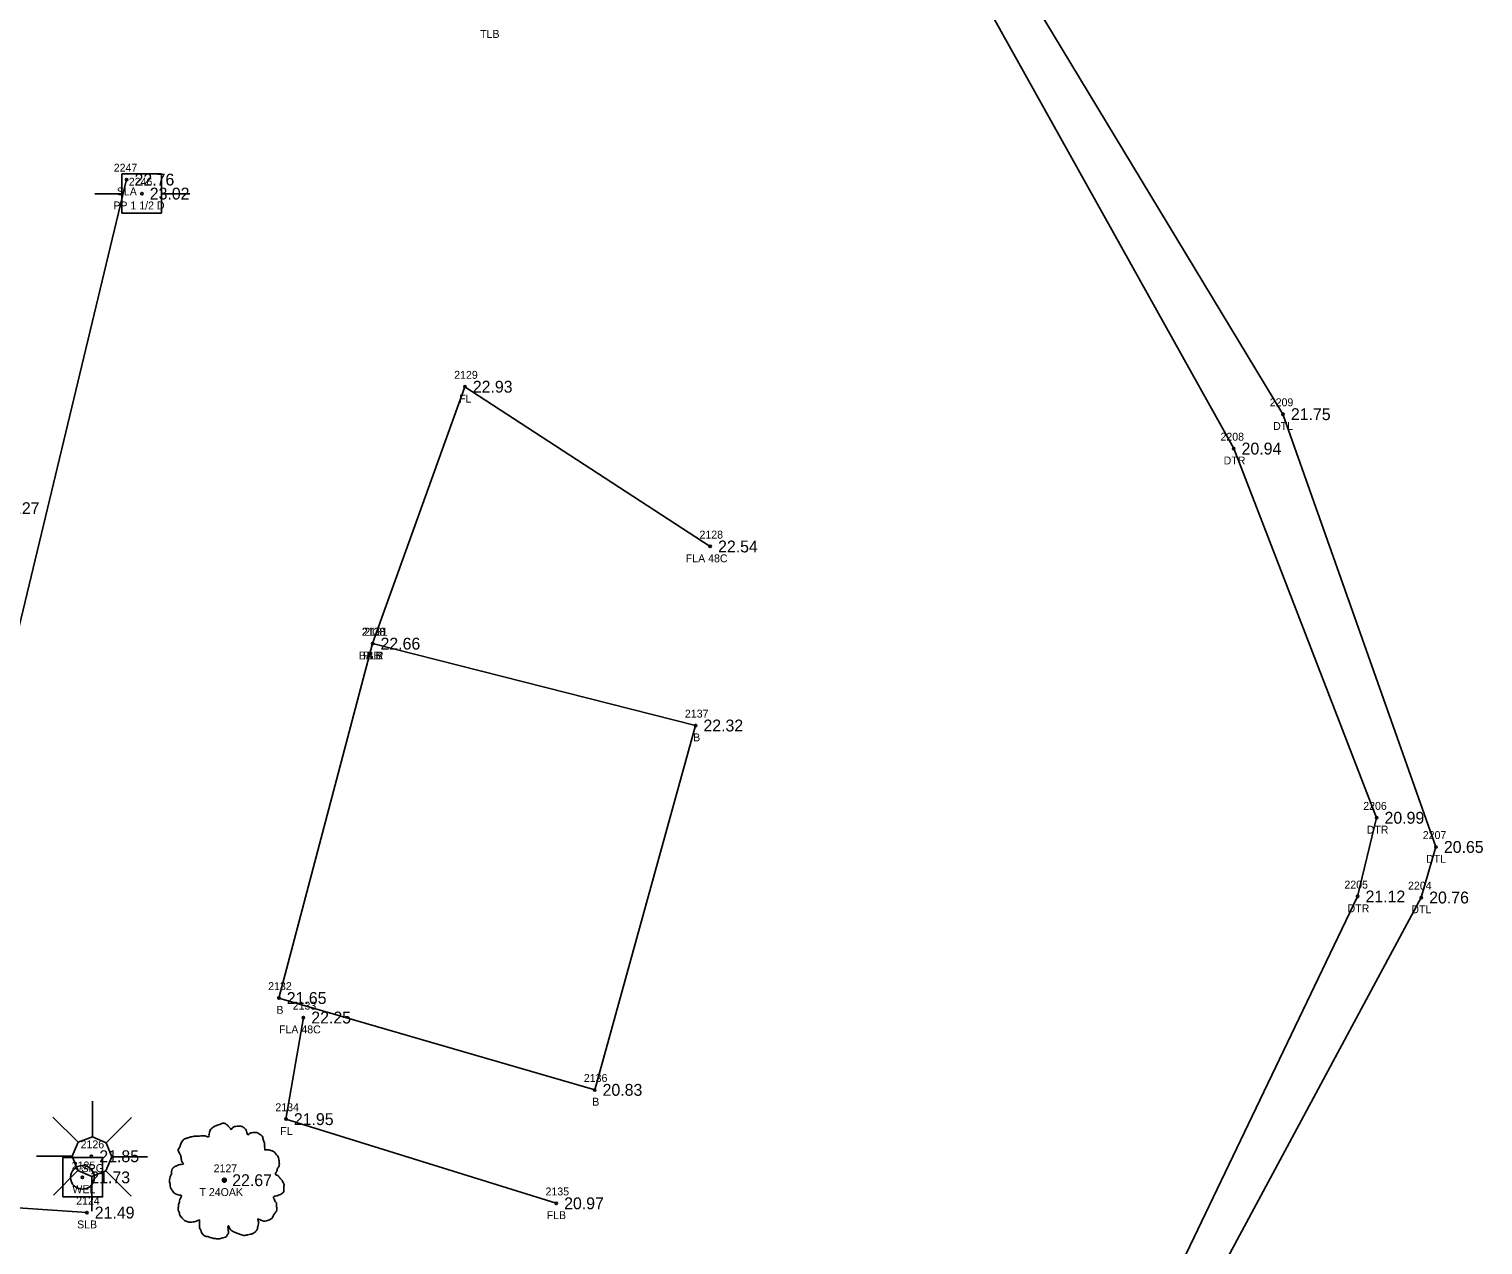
# Model space of a CAD drawing. Extents: x 2654414 to 2656963, y 761776 to 764965.
# Drawn here: x 2655506 to 2655689.7, y 762096.2 to 762249.9 of the extents above; entities that cross this region are included whole.
import ezdxf

# ---------------------------------------------------------------- set-up
doc = ezdxf.new("R2010")
doc.units = 0
for name, color, linetype in [('RD_EX_Bldg', 7, 'Continuous'), ('RD_EX_Bldg_txCode', 7, 'Continuous'), ('RD_EX_BldgApp', 7, 'Continuous'), ('RD_EX_BldgApp_txCode', 7, 'Continuous'), ('RD_EX_Fence_Other', 7, 'Continuous'), ('RD_EX_Fence_Other_txCode', 7, 'Continuous'), ('RD_EX_H2O', 7, 'Continuous'), ('RD_EX_H2O_txCode', 7, 'Continuous'), ('RD_EX_SU_H2O', 7, 'Continuous'), ('RD_EX_TX_Bldg_ELEV', 7, 'Continuous'), ('RD_EX_TX_BldgApp_ELEV', 7, 'Continuous'), ('RD_EX_TX_Fence_Other_ELEV', 7, 'Continuous'), ('RD_EX_TX_H2O_ELEV', 7, 'Continuous'), ('RD_EX_TX_UT_ELEV', 7, 'Continuous'), ('RD_EX_TX_VEG_ELEV', 7, 'Continuous'), ('RD_EX_UT', 7, 'Continuous'), ('RD_EX_UT_txCode', 7, 'Continuous'), ('RD_EX_VEG', 7, 'Continuous'), ('RD_EX_VEG_txCode', 7, 'Continuous'), ('RD_HC_Survey_ELEV', 7, 'Continuous'), ('RD_SMD_Locator', 7, 'Continuous')]:
    doc.layers.add(name, color=color, linetype=linetype)

msp = doc.modelspace()

# ---------------------------------------------------------------- linework, layer by layer
at = {"layer": 'RD_EX_Bldg'}
msp.add_lwpolyline([(2655549.36, 762172.23), (2655537.51, 762127.44), (2655577.42, 762115.83), (2655590.16, 762161.88), (2655549.36, 762172.23)], dxfattribs=at)
at = {"layer": 'RD_EX_BldgApp'}
for p, q in [((2655513.95, 762109.9), (2655513.95, 762114.41)), ((2655512.16, 762109.2), (2655508.97, 762112.39)), ((2655515.7, 762109.13), (2655518.89, 762112.33)), ((2655511.41, 762107.44), (2655506.89, 762107.44)), ((2655516.42, 762107.36), (2655520.92, 762107.36)), ((2655512.13, 762105.63), (2655509.02, 762102.51)), ((2655513.9, 762104.9), (2655513.9, 762100.48)), ((2655515.64, 762105.6), (2655518.83, 762102.41))]:
    msp.add_line(p, q, dxfattribs=at)
msp.add_lwpolyline([(2655512.16, 762109.2), (2655513.95, 762109.9), (2655515.7, 762109.13), (2655516.42, 762107.36), (2655515.64, 762105.6), (2655513.9, 762104.9), (2655512.13, 762105.63), (2655511.41, 762107.44)], close=True, dxfattribs=at)
at = {"layer": 'RD_EX_BldgApp_txCode'}
msp.add_circle((2655512.69, 762104.77), 0.15, dxfattribs=at)
at = {"layer": 'RD_EX_Fence_Other'}
for points in [[(2655592.01, 762184.51), (2655561.02, 762204.7), (2655549.36, 762172.23)], [(2655540.61, 762124.97), (2655538.41, 762112.13), (2655572.56, 762101.49)]]:
    msp.add_lwpolyline(points, dxfattribs=at)
at = {"layer": 'RD_EX_H2O'}
for points in [[(2655458.25, 762004.65), (2655489.16, 762003.6), (2655538.42, 762005.59), (2655556.05, 762013.17), (2655587.88, 762051.39), (2655643.4, 762074.04), (2655655.85, 762091.76), (2655681.86, 762140.14), (2655683.72, 762146.53), (2655664.39, 762201.23), (2655621.98, 762271.36), (2655558.86, 762321.08)], [(2655459.71, 762010.57), (2655488.92, 762008.22), (2655537.08, 762011.25), (2655554.9, 762018.55), (2655583.72, 762054.68), (2655639.44, 762078.76), (2655651.66, 762094.07), (2655673.82, 762140.27), (2655676.22, 762150.22), (2655658.16, 762196.88), (2655618.83, 762267.48), (2655556.47, 762317.07), (2655558.86, 762321.08)]]:
    msp.add_lwpolyline(points, dxfattribs=at)
at = {"layer": 'RD_EX_SU_H2O'}
msp.add_lwpolyline([(2655510.23, 762102.3), (2655510.23, 762107.3), (2655515.23, 762107.3), (2655515.23, 762102.3)], close=True, dxfattribs=at)
msp.add_circle((2655512.69, 762104.77), 1.5, dxfattribs=at)
at = {"layer": 'RD_EX_UT'}
for p, q in [((2655522.69, 762231.62), (2655517.69, 762231.62)), ((2655517.69, 762231.62), (2655517.69, 762226.62)), ((2655522.69, 762226.62), (2655522.69, 762231.62)), ((2655514.26, 762229.06), (2655517.73, 762229.06)), ((2655522.62, 762229.06), (2655526.26, 762229.06)), ((2655517.69, 762226.62), (2655522.69, 762226.62))]:
    msp.add_line(p, q, dxfattribs=at)
at = {"layer": 'RD_EX_VEG'}
msp.add_line((2655518.28, 762230.88), (2655497.58, 762144.9), dxfattribs=at)
msp.add_lwpolyline([(2655499.64, 762109.41), (2655498.94, 762101.31), (2655513.25, 762100.32)], dxfattribs=at)
for centre, radius in [((2655530.62, 762104.41), 0.25), ((2655530.61, 762104.39), 0.0001)]:
    msp.add_circle(centre, radius, dxfattribs=at)
for points in [[(2655530.75, 762111.58), (2655530.45, 762111.6), (2655530.13, 762111.5), (2655529.88, 762111.4), (2655529.65, 762111.33), (2655529.43, 762111.23), (2655529.13, 762111.05), (2655528.9, 762110.85), (2655528.78, 762110.6), (2655528.73, 762110.38), (2655528.68, 762110.1), (2655528.68, 762109.93), (2655528.55, 762109.9), (2655528.4, 762109.93), (2655528.15, 762110), (2655527.9, 762110), (2655527.65, 762110), (2655527.3, 762109.98), (2655526.95, 762109.98), (2655526.68, 762109.93), (2655526.35, 762109.88), (2655525.98, 762109.75), (2655525.63, 762109.63), (2655525.33, 762109.38), (2655525.08, 762108.9), (2655524.95, 762108.55), (2655524.8, 762108.3), (2655524.95, 762107.85), (2655525.13, 762107.5), (2655525.15, 762107.3), (2655525.23, 762106.88), (2655525.33, 762106.66), (2655525.45, 762106.46), (2655525.38, 762106.43), (2655525, 762106.38), (2655524.7, 762106.28), (2655524.28, 762106.06), (2655524.05, 762105.83), (2655523.95, 762105.51), (2655523.93, 762105.16), (2655523.83, 762104.96), (2655523.75, 762104.68), (2655523.73, 762104.61), (2655523.68, 762104.28), (2655523.78, 762103.83), (2655523.8, 762103.48), (2655523.93, 762103.26), (2655524.08, 762103.08), (2655524.25, 762102.83), (2655524.65, 762102.61), (2655524.98, 762102.51), (2655525.18, 762102.48), (2655525, 762101.98), (2655524.95, 762101.63), (2655524.83, 762101.23), (2655524.83, 762101.16), (2655524.78, 762100.68), (2655524.93, 762100.36), (2655525, 762099.98), (2655525.18, 762099.76), (2655525.45, 762099.46), (2655525.78, 762099.23), (2655526.28, 762099.11), (2655526.68, 762099.13), (2655527.25, 762099.31), (2655527.5, 762099.38), (2655527.48, 762099.21), (2655527.5, 762098.83), (2655527.5, 762098.41), (2655527.65, 762098.08), (2655527.75, 762097.81), (2655527.9, 762097.56), (2655528.23, 762097.33), (2655528.63, 762097.26), (2655529.05, 762097.11), (2655529.5, 762097.03), (2655530, 762097.01), (2655530.6, 762097.16), (2655530.88, 762097.28), (2655530.98, 762097.46), (2655531.17, 762097.83), (2655531.12, 762098.06), (2655531.15, 762098.66), (2655531.25, 762098.48), (2655531.42, 762098.13), (2655531.92, 762097.83), (2655532.32, 762097.66), (2655532.8, 762097.51), (2655533.1, 762097.43), (2655533.57, 762097.51), (2655533.95, 762097.58), (2655534.32, 762097.71), (2655534.62, 762097.98), (2655534.8, 762098.26), (2655534.85, 762098.53), (2655534.92, 762098.91), (2655534.97, 762099.08)], [(2655534.97, 762099.08), (2655534.9, 762099.26), (2655534.85, 762099.51), (2655534.92, 762099.48), (2655535.1, 762099.43), (2655535.37, 762099.31), (2655535.6, 762099.23), (2655535.92, 762099.26), (2655536.2, 762099.36), (2655536.65, 762099.63), (2655536.92, 762100.11), (2655537.2, 762100.51), (2655537.27, 762100.83), (2655537.22, 762101.06), (2655537.2, 762101.56), (2655537, 762101.81), (2655536.95, 762101.93), (2655536.85, 762102.33), (2655536.92, 762102.38), (2655537.2, 762102.43), (2655537.57, 762102.56), (2655537.85, 762102.68), (2655538.07, 762102.86), (2655538.15, 762103.08), (2655538.12, 762103.48), (2655538.17, 762103.88), (2655538.1, 762104.03), (2655538, 762104.18), (2655537.92, 762104.38), (2655537.77, 762104.53), (2655537.67, 762104.68), (2655537.57, 762104.78), (2655537.45, 762104.93), (2655537.27, 762105.06), (2655537.12, 762105.11), (2655537.07, 762105.26), (2655537.22, 762105.46), (2655537.27, 762105.56), (2655537.3, 762105.78), (2655537.52, 762106.13), (2655537.57, 762106.53), (2655537.52, 762106.95), (2655537.47, 762107.23), (2655537.32, 762107.5), (2655537.12, 762107.75), (2655537, 762107.93), (2655536.82, 762108.05), (2655536.5, 762108.18), (2655536.25, 762108.23), (2655535.9, 762108.23), (2655535.7, 762108.28), (2655535.72, 762108.33), (2655535.72, 762108.48), (2655535.72, 762108.75), (2655535.65, 762109.2), (2655535.5, 762109.7), (2655535.5, 762109.73), (2655535.4, 762109.98), (2655535.17, 762110.18), (2655535, 762110.28), (2655534.8, 762110.4), (2655534.55, 762110.43), (2655534.25, 762110.43), (2655533.97, 762110.38), (2655533.77, 762110.28), (2655533.6, 762110.15), (2655533.52, 762110.3), (2655533.42, 762110.6), (2655533.37, 762110.75), (2655533.22, 762110.93), (2655533, 762111.13), (2655532.55, 762111.25), (2655531.92, 762111.18), (2655531.62, 762110.98), (2655531.47, 762110.8), (2655531.42, 762110.93), (2655531.22, 762111.13), (2655531.12, 762111.3), (2655530.95, 762111.43), (2655530.8, 762111.53), (2655530.7, 762111.58)]]:
    msp.add_spline(points, degree=3, dxfattribs=at)
at = {"layer": 'RD_SMD_Locator'}
for centre in [(2655518.28, 762230.88), (2655520.2, 762229.11), (2655561.02, 762204.7), (2655664.39, 762201.23), (2655658.16, 762196.88), (2655592.01, 762184.51), (2655549.36, 762172.23), (2655549.36, 762172.23), (2655549.36, 762172.23), (2655590.16, 762161.88), (2655676.22, 762150.22), (2655683.72, 762146.53), (2655673.82, 762140.27), (2655681.86, 762140.14), (2655537.51, 762127.44), (2655540.61, 762124.97), (2655577.42, 762115.83), (2655538.41, 762112.13), (2655513.83, 762107.44), (2655530.62, 762104.41), (2655572.56, 762101.49), (2655513.25, 762100.32)]:
    msp.add_circle(centre, 0.15, dxfattribs=at)

# ---------------------------------------------------------------- texts
at = {"layer": 'RD_EX_Bldg_txCode'}
for s, p in [('2138', (2655548.02, 762173.23)), ('2131', (2655548.3, 762173.23)), ('BA R', (2655547.61, 762170.23)), ('BB', (2655548.58, 762170.23)), ('2137', (2655588.82, 762162.88)), ('B', (2655589.86, 762159.88)), ('2132', (2655536.16, 762128.44)), ('B', (2655537.2, 762125.44)), ('2136', (2655576.05, 762116.83)), ('B', (2655577.11, 762113.83))]:
    msp.add_text(s, height=1, dxfattribs=at).set_placement(p)
at = {"layer": 'RD_EX_BldgApp_txCode'}
for s, p in [('2126', (2655512.46, 762108.44)), ('2125', (2655511.34, 762105.77)), ('SPG', (2655512.58, 762105.44)), ('WEL', (2655511.42, 762102.77))]:
    msp.add_text(s, height=1, dxfattribs=at).set_placement(p)
at = {"layer": 'RD_EX_Fence_Other_txCode'}
for s, p in [('2129', (2655559.67, 762205.7)), ('FL', (2655560.29, 762202.7)), ('2128', (2655590.66, 762185.51)), ('FLA 48C', (2655588.93, 762182.51)), ('2130', (2655547.98, 762173.23)), ('FLB', (2655548.16, 762170.23)), ('2133', (2655539.26, 762125.97)), ('FLA 48C', (2655537.53, 762122.97)), ('2134', (2655537.07, 762113.13)), ('FL', (2655537.68, 762110.13)), ('2135', (2655571.21, 762102.49)), ('FLB', (2655571.35, 762099.49))]:
    msp.add_text(s, height=1, dxfattribs=at).set_placement(p)
at = {"layer": 'RD_EX_H2O_txCode'}
for s, p in [('2209', (2655662.72, 762202.23)), ('2208', (2655656.49, 762197.88)), ('DTL', (2655663.14, 762199.23)), ('DTR', (2655656.89, 762194.88)), ('2206', (2655674.53, 762151.22)), ('DTR', (2655674.96, 762148.22)), ('2207', (2655682.05, 762147.53)), ('DTL', (2655682.47, 762144.53)), ('2205', (2655672.15, 762141.27)), ('2204', (2655680.19, 762141.14)), ('DTR', (2655672.55, 762138.27)), ('DTL', (2655680.61, 762138.14))]:
    msp.add_text(s, height=1, dxfattribs=at).set_placement(p)
at = {"layer": 'RD_EX_TX_Bldg_ELEV'}
for s, p in [('22.66', (2655550.36, 762171.48)), ('22.66', (2655550.36, 762171.48)), ('22.32', (2655591.16, 762161.13)), ('21.65', (2655538.51, 762126.69)), ('20.83', (2655578.42, 762115.08))]:
    msp.add_text(s, height=1.5, dxfattribs=at).set_placement(p)
at = {"layer": 'RD_EX_TX_BldgApp_ELEV'}
for s, p in [('21.85', (2655514.83, 762106.69)), ('21.73', (2655513.69, 762104.02))]:
    msp.add_text(s, height=1.5, dxfattribs=at).set_placement(p)
at = {"layer": 'RD_EX_TX_Fence_Other_ELEV'}
for s, p in [('22.93', (2655562.02, 762203.95)), ('22.54', (2655593.01, 762183.76)), ('22.66', (2655550.36, 762171.48)), ('22.25', (2655541.61, 762124.22)), ('21.95', (2655539.41, 762111.38)), ('20.97', (2655573.56, 762100.74))]:
    msp.add_text(s, height=1.5, dxfattribs=at).set_placement(p)
at = {"layer": 'RD_EX_TX_H2O_ELEV'}
for s, p in [('21.75', (2655665.39, 762200.48)), ('20.94', (2655659.16, 762196.13)), ('20.99', (2655677.22, 762149.47)), ('20.65', (2655684.72, 762145.78)), ('21.12', (2655674.82, 762139.52)), ('20.76', (2655682.86, 762139.39))]:
    msp.add_text(s, height=1.5, dxfattribs=at).set_placement(p)
at = {"layer": 'RD_EX_TX_UT_ELEV'}
msp.add_text('23.27', height=1.5, dxfattribs=at).set_placement((2655502.25, 762188.6))
at = {"layer": 'RD_EX_TX_VEG_ELEV'}
for s, p in [('22.76', (2655519.28, 762230.13)), ('22.67', (2655531.62, 762103.66)), ('21.49', (2655514.25, 762099.57))]:
    msp.add_text(s, height=1.5, dxfattribs=at).set_placement(p)
at = {"layer": 'RD_EX_UT_txCode'}
for s, p in [('2246', (2655518.55, 762230.11)), ('PP 1 1/2 D', (2655516.6, 762227.11))]:
    msp.add_text(s, height=1, dxfattribs=at).set_placement(p)
at = {"layer": 'RD_EX_VEG_txCode'}
for s, p in [('TLB', (2655562.94, 762248.79)), ('2247', (2655516.65, 762231.88)), ('SLA', (2655517.04, 762228.88)), ('2127', (2655529.27, 762105.41)), ('T 24OAK', (2655527.48, 762102.41)), ('2124', (2655511.9, 762101.32)), ('SLB', (2655512.02, 762098.32))]:
    msp.add_text(s, height=1, dxfattribs=at).set_placement(p)
at = {"layer": 'RD_HC_Survey_ELEV'}
msp.add_text('23.02', height=1.5, dxfattribs=at).set_placement((2655521.2, 762228.36))

doc.saveas('drawing.dxf')
